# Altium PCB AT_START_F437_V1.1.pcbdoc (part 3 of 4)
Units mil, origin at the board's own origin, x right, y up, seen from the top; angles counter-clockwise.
Board outline 10746.75 x 3533.35 mil, 2 copper layers (Top Layer, Bottom Layer); 198 components, 235 nets, 885 pads, 1100 vias.
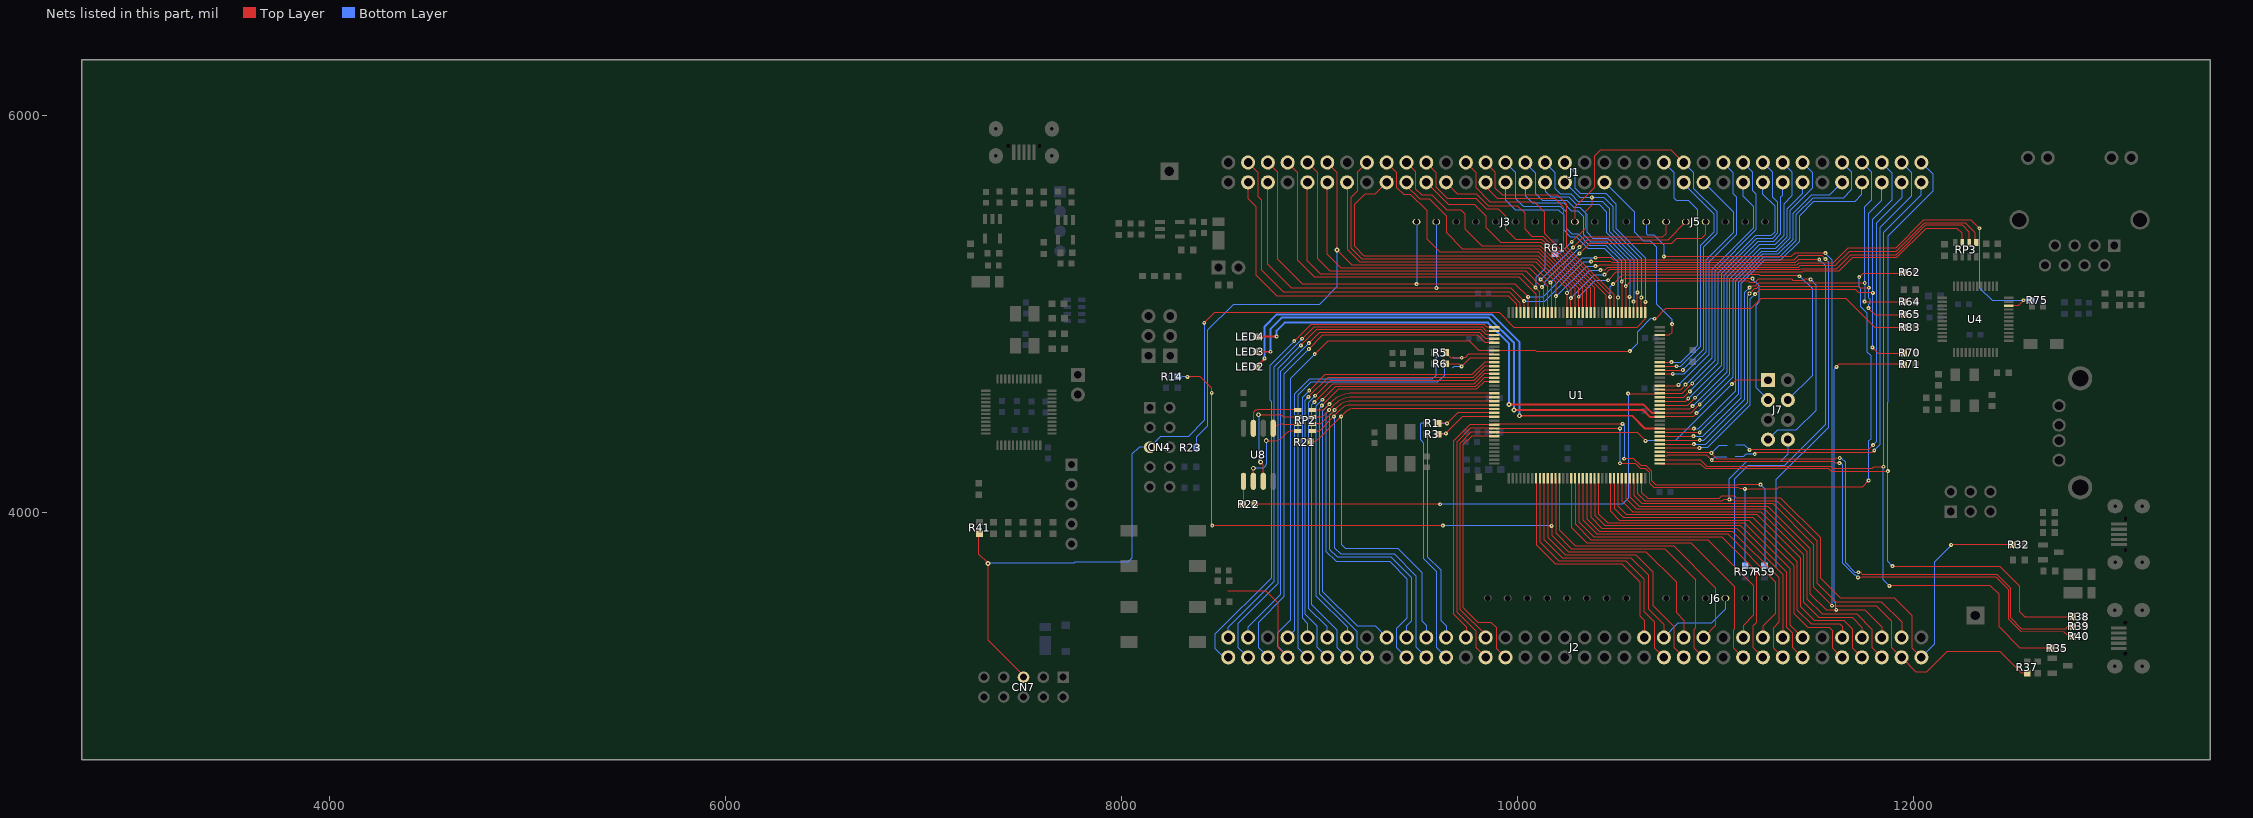
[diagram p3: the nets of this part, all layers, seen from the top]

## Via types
v1: diameter 19.69, hole 7.87, Top Layer to Bottom Layer, 1002 vias
v2: diameter 23.62, hole 11.81, Top Layer to Bottom Layer, 48 vias
v3: diameter 24, hole 12, Top Layer to Bottom Layer, 18 vias
v4: diameter 19.68, hole 7.87, Top Layer to Bottom Layer, 16 vias
v5: diameter 35.43, hole 19.69, Top Layer to Bottom Layer, 12 vias
v6: diameter 27.56, hole 15.75, Top Layer to Bottom Layer, 2 vias
v7: diameter 35.43, hole 19.68, Top Layer to Bottom Layer, 2 vias

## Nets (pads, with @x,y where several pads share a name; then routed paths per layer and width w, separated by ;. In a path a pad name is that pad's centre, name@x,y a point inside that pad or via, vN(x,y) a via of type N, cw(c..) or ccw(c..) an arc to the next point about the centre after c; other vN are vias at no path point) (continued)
PA14/SWCLK: CN4.5 CN7.5 J1.37 R41.1 U1.109 | length 6334.4
  Top Layer w6: R41.1@7280,3888.07 7280,3786.07 v2(7325.75,3740.36) 7325.8,3352.26 7505,3173.07 CN7.5@7505,3165.97 ; v1(8417.75,4955.35) 8470.3,5007.86 9907.4,5007.86 9980.9,4934.36 10603.03,4934.36 10644.2,4975.54 U1.109@10644.23,5007.69 10644.7,5008.16 v1@10644.7,5061.36
  Bottom Layer w6: v2@7325.7,3740.36 7757.8,3740.36 7763.8,3746.36 8030.8,3746.36 8054.8,3770.36 8054.8,4293.47 8088.8,4327.56 ; 8090.27,4327.36 CN4.5@8142.77,4327.36 8142.78,4329.84 8194.3,4381.36 8336.5,4381.36 8417.8,4462.66 v1(8417.75,4955.35) ; J1.37@10238.7,5765.06 10287.8,5715.97 10287.8,5637.27 10315.7,5609.36 10443.8,5609.36 10495.8,5557.36 10495.8,5433.97 10644.7,5285.06 v1@10644.7,5061.36
  other v1: 10644.75,5061.35
PA15: J1.38 R61.1 U1.110 | length 1263.8
  Top Layer w6: v1(10273.42,5364.4) 10340.4,5431.36 10340.4,5515.27 10374.5,5549.47 v1(10374.54,5589.36) ; U1.110@10624.54,5007.69 10624.7,5007.86 v1@10624.7,5083.36
  Bottom Layer w6: R61.1@10188.8,5306.86 10215.9,5306.86 v1(10273.42,5364.4) ; J1.38@10238.7,5665.06 10314.4,5589.36 v1(10374.54,5589.36) ; v1(10374.54,5589.36) 10435.8,5589.36 10479.8,5545.36 10479.8,5425.56 10624.7,5280.66 v1@10624.7,5083.36
  other v1: 10624.75,5083.35
PB0: J2.46 J6.4 U1.46 | length 1685.8
  Top Layer w6: U1.46@10132.42,4171.06 10132.4,3861.66 10224.2,3769.86 10572.3,3769.86 10659.5,3682.66 10659.5,3512.57 10738.7,3433.47 J2.46@10738.72,3366.46
  Bottom Layer w6: J2.46@10738.72,3366.46 10809.6,3437.36 10977.8,3437.36 11049.4,3508.97 J6.4@11049.36,3565.36
PB1: J2.47 U1.47 | length 1397.4
  Top Layer w6: U1.47@10152.1,4171.06 10152.1,3872.26 10239.5,3784.86 10595.3,3784.86 10682,3698.16 10682,3529.16 10787.8,3423.36 10787.8,3317.47 J2.47@10838.72,3266.46
PB2/BOOT1: J2.48 R14.2 U1.48 | length 3916.5
  Top Layer w6: v1(8332.75,4682.35) 8398,4682.36 8455.5,4624.86 v1(8455.49,4601.97) ; v1(8457.75,3931.36) v1(9622.75,3931.36) ; U1.48@10171.79,4171.06 10171.7,4171.06 10171.7,3930.36 10171.7,3883.36 10255.6,3799.47 10647.6,3799.47 10799.8,3647.26 10799.8,3493.26 10838.7,3454.36 J2.48@10838.72,3366.46
  Bottom Layer w6: R14.2@8282.3,4683.36 v1(8332.75,4682.35) ; v1(8455.49,4601.97) 8455.49,3933.62 v1(8457.75,3931.36) ; v1(9622.75,3931.36) 9623.75,3930.36 v1(10171.75,3930.36)
PB3: J1.61 J5.4 R23.2 U1.133 | length 4256.2
  Top Layer w6: J1.61@9038.7,5765.06 9087.8,5715.97 v3(9087.75,5323.35) 9161.8,5249.36 10074.74,5249.36 v1(10165.09,5159.02) ; v1(10165.09,5159.02) 10171.8,5152.36 U1.133@10171.79,5007.69 ; v1(10313.22,5306.09) 10364.8,5357.66 10778.9,5357.66 10803.7,5382.56 10928.6,5382.56 10949.3,5403.16 J5.4@10949.35,5465.35
  Bottom Layer w6: R23.2@8377.3,4325.56 8377.2,4376.97 8433.4,4433.36 8433.4,4918.06 8563,5047.66 8998.1,5047.66 9087.8,5137.36 v3@9087.8,5323.56 ; v1(10165.09,5159.02) 10312.17,5306.09 v1(10313.22,5306.09)
PB4: J1.62 J5.6 U1.134 | length 2465.4
  Top Layer w6: J1.62@9038.7,5665.06 9035.8,5662.06 9035.8,5305.36 9107.8,5233.36 10057.73,5233.36 v1(10116.22,5174.88) 10151.74,5139.35 ; 10151.7,5139.36 10151.7,5008.06 U1.134@10152.1,5007.69 ; v1(10280.12,5336.81) 10333.7,5390.36 10733.2,5390.36 10749.3,5406.47 J5.6@10749.35,5465.35
  Bottom Layer w6: v1(10116.22,5174.88) 10118.18,5174.87 v1(10280.12,5336.81)
PB5: J1.63 J5.5 U1.135 | length 2701.5
  Top Layer w6: J1.63@8938.7,5765.06 8987.8,5715.97 8987.8,5281.36 9051.8,5217.36 10041,5217.36 v1(10122.52,5135.88) 10132.4,5125.97 U1.135@10132.42,5007.69 ; v1(10312.43,5337.6) 10350.3,5375.47 10759.4,5375.47 J5.5@10849.35,5465.35
  Bottom Layer w6: v1(10122.52,5135.88) 10140.65,5154 10140.65,5165.42 10312.43,5337.21 v1(10312.43,5337.6)
PB6: J1.64 U1.136 | length 1936.9
  Top Layer w6: J1.64@8938.7,5665.06 8938.7,5268.47 9005.8,5201.36 10022.7,5201.36 10090.7,5133.36 10112.7,5111.36 U1.136@10112.73,5007.69
  Bottom Layer w6: v1@10090.7,5133.36 10090.7,5183.66 10135.7,5228.66 10135.7,5312.27
  other v1: 10090.75,5133.35
PB7: J1.65 U1.137 | length 1882.2
  Top Layer w6: J1.65@8838.7,5765.06 8889.8,5713.97 8889.8,5271.27 8975.8,5185.36 10008.9,5185.36 10093.1,5101.06 U1.137@10093.05,5007.69
PB8: J1.67 J3.10 U1.139 | length 5522.3
  Top Layer w6: J1.67@8738.7,5764.56 8787.8,5715.97 8787.8,5277.27 8913.8,5151.36 9988.8,5151.36 v1(10053.12,5087.01) 10053.1,5008.16 U1.139@10053.7,5007.56 ; v1(10393.75,5284.35) 10473.91,5284.35 10486.39,5271.87 11394.17,5271.87 11416.96,5294.66 11536.98,5294.66 v1(11553.92,5277.71)
  Bottom Layer w6: J3.10@9489.36,5465.36 9489.4,5393.77 9489.7,5393.47 v1@9489.7,5151.36 ; v1(10053.12,5087.01) 10129.44,5087.01 10326.8,5284.36 v1(10393.75,5284.35) ; 11306.54,3721.67 11306.54,4164.71 11570.8,4428.97 11570.8,5260.9 v1@11553.97,5277.72
  other v1: 9489.75,5151.35
PB9: J1.68 J3.9 U1.140 | length 5621
  Top Layer w6: J1.68@8738.7,5664.56 8738.7,5252.36 8859.8,5131.36 9966.7,5131.36 v1(10032.75,5065.35) 10032.8,5008.77 U1.140@10034,5007.56 ; v1(10370.75,5264.35) 10470.75,5264.35 10476.75,5258.35 11400.21,5258.35 11416.81,5274.96 v1(11523.19,5274.96)
  Bottom Layer w6: v1(9589.35,5131.35) J3.9@9589.36,5465.36 ; v1(10032.75,5065.35) 10135.75,5065.35 10334.75,5264.35 v1(10370.75,5264.35) ; 11095.8,3722.47 11095.8,4168.31 11165.05,4237.55 11347.86,4237.55 11554.8,4444.49 11554.8,5243.41 v1(11523.19,5274.96)
PB10: J2.69 J5.7 R37.1 U1.69 | length 5583.1
  Top Layer w6: U1.69@10585.17,4171.06 10585.2,4084.47 10626.4,4043.36 11287.9,4043.36 11492.9,3838.36 11492.9,3623.26 11588.2,3527.97 11810.2,3527.97 11887.8,3450.26 11887.8,3317.47 J2.69@11938.72,3266.46 12010.9,3194.26 12066.9,3194.26 12170.1,3297.47 12433.3,3297.47 12542.7,3188.07 R37.1@12572.7,3188.07 ; v1(10738.74,5290.72) 11382.48,5290.66 11401.45,5309.63 11552.35,5309.63 v1(11554.32,5307.66)
  Bottom Layer w6: J5.7@10649.35,5465.35 10649.3,5406.86 10655.6,5400.66 10686.7,5400.66 10738.7,5348.66 v1@10738.7,5290.77 ; v1(11554.32,5307.66) 11586.63,5275.35 11586.63,3527.91 v1(11587.37,3527.16)
PB11: J2.70 J7.8 U1.70 | length 2418.8
  Top Layer w6: U1.70@10604.86,4171.06 10604.9,4094.36 10642.6,4056.66 11034.3,4056.66 ; 11029.4,4056.66 11034.3,4056.66 ; v1(11068.91,4063.41) 11041.08,4063.45 11034.3,4056.66 ; v1(11068.91,4063.41) 11090.58,4063.41 11096.88,4057.1 11307.66,4057.1 11509.8,3854.97 11509.8,3643.66 11605.4,3548.07 11837.3,3548.07 11938.7,3446.66 J2.70@11938.72,3366.46
  Bottom Layer w6: v1(11068.91,4063.41) 11068.87,4167.78 11155.59,4254.5 11327.32,4254.5 11364.4,4291.49 J7.8@11364.4,4365.97
PB12/OTG2_ID: J1.1 R38.1 U1.73 | length 4427.2
  Top Layer w6: U1.73@10718.05,4244.88 10718.73,4244.25 10923.13,4244.25 10946.95,4220.43 11569.56,4220.43 11583.53,4206.47 v1@11869.5,4206.47 ; v1@11892.73,3727.34 12434.89,3727.34 12533.8,3628.43 12533.8,3498.8 12560.24,3472.36 R38.1@12807,3472.36
  Bottom Layer w6: 11868.8,4554.36 11868.8,5392.77 12095.8,5619.86 12095.8,5707.97 J1.1@12038.7,5765.06 ; 11869.75,4553.36 11869.52,4553.13 v1(11869.52,4206.43) 11869.52,3750.57 v1(11892.76,3727.32)
PB13/OTG2_VBUS: J1.2 R35.1 U1.74 | length 4325.7
  Top Layer w6: U1.74@10718.05,4264.56 10718.32,4264.35 10922.34,4264.35 10954.26,4232.43 11580.7,4232.43 11592.13,4221.01 11791.1,4221.01 11798.98,4228.89 v1(11847.45,4228.89) ; v1@11876.99,3627.67 12387.2,3627.67 12430.97,3583.91 12430.97,3420.4 12537.8,3313.57 R35.1@12697.2,3313.57
  Bottom Layer w6: v1@11847.4,4228.86 11848.8,4230.27 11848.8,5413.06 12038.7,5602.97 J1.2@12038.7,5665.06 ; v1(11847.45,4228.89) 11847.45,3657.19 v1(11877,3627.64)
PB14/OTG2_D-: R40.1 U1.75 | length 2931.1
  Top Layer w6: U1.75@10718.05,4284.24 10755.7,4284.24 10759.05,4287.59 10955.1,4287.59 v1(10980.26,4262.38) 10988.06,4254.64 11597.51,4254.64 11605.14,4247.01 v1(11624.45,4247.01) ; v1(11718.62,3670.19) 11732.05,3670.23 11736.38,3674.57 12413.03,3674.57 12477.67,3609.92 12477.67,3460.74 12541.21,3397.07 12757.8,3395.18 12784.61,3372.57 12804.63,3372.57 R40.1@12804.85,3372.35
  Bottom Layer w6: v1(10980.26,4262.38) 10998.25,4280.36 11055.6,4280.36 ; v1(11624.45,4247.01) 11633.91,4247.01 11639.42,4241.49 11639.42,3743.08 11699.07,3683.44 11705.37,3683.44 v1(11718.62,3670.19)
PB14_E: J1.3 | length 2265.7
  Top Layer w6: v1@11197.39,4292.35 11203.39,4298.35 11787.3,4298.35 v1(11800.57,4311.63)
  Bottom Layer w6: 11100,4280.36 11140.5,4280.36 11152.4,4292.36 v1@11197.4,4292.36 ; v1@11800.52,4311.64 11831.8,4342.92 11831.8,5436.97 11988.8,5593.97 11988.8,5714.97 J1.3@11938.7,5765.06
  other v1: 11197.35,4292.31
PB15/OTG2_D+: R39.1 U1.76 | length 2949.3
  Top Layer w6: U1.76@10718.05,4303.94 10753.39,4303.94 10757.73,4299.59 10976.09,4299.59 11009.14,4266.64 11603.1,4266.64 11609.48,4273.01 v1(11626.42,4273.01) ; v1(11720.59,3696.2) 11731.65,3696.16 11741.25,3686.57 12418.1,3686.57 12489.67,3614.99 12489.67,3465.69 12546.35,3409.02 12765.13,3409.02 12778.48,3422.37 R39.1@12804.83,3422.37
  Bottom Layer w6: v1(10978.29,4298.23) 11018.47,4338.36 11057.6,4338.36 ; v1(11626.42,4273.01) 11634.91,4273.01 11654,4253.92 11654,3745.48 11703.28,3696.2 v1(11720.59,3696.2)
PB15_E: J1.4 | length 2099
  Top Layer w6: v1(11171.75,4314.35) 11770.94,4314.36 v1@11794.61,4338.03
  Bottom Layer w6: 11102,4338.36 11147.8,4338.36 v1(11171.75,4314.35) ; v1@11794.61,4338.03 11813.8,4357.23 11813.8,5461.47 11938.7,5586.47 J1.4@11938.7,5665.06
  other v1: 11794.66,4338.02
PC0: J2.26 R59.1 U1.26 | length 3281.1
  Top Layer w6: J2.26@9738.72,3366.46 9739.8,3367.47 9739.8,3420.97 9673.8,3486.97 9673.8,4358.47 9757,4441.66 U1.26@9881.43,4441.73 9885.1,4445.36 v1@10529.7,4445.36 ; v1(10537.75,4269.35) 10587.05,4269.35 10623.45,4232.95 10650.39,4232.95 10677.85,4205.49 10677.85,4158.97 10701.2,4135.62 11106.06,4135.62 11107.92,4137.48 11225.72,4137.48 v1(11226.51,4138.27)
  Bottom Layer w6: v1@10529.75,4445.35 10537.75,4437.35 v1(10537.75,4269.35) ; v1(11226.51,4138.27) 11246.6,4118.17 R59.1@11246.6,3729.01
  other v1: 10529.75,4445.35
PC1: J2.27 R57.1 R62.1 U1.27 | length 5214
  Top Layer w6: J2.27@9838.72,3266.46 9787.8,3317.47 9787.8,3401.26 9691.5,3497.57 9691.5,4351.86 9761.7,4422.06 9881.4,4422.06 9881.8,4422.36 v1@10516.7,4422.36 ; v1@10516.7,4246.36 10593.07,4246.36 10618.48,4220.95 10645.42,4220.95 10665.85,4200.52 10665.85,4147.72 10689.95,4123.62 11117.7,4123.62 11123.95,4117.36 v1(11147.71,4117.38) 11310.41,4117.36 11319.1,4126.05 11739.1,4126.05 v1(11772.59,4159.54) ; v1(11724.92,5186.31) 11745.83,5207.19 R62.1@11948.12,5207.19
  Bottom Layer w6: v1(10516.75,4246.35) v1@10516.75,4422.35 ; v1@11147.76,4117.39 11147.76,3728.81 R57.1@11149.7,3726.86 ; v1(11724.92,5186.31) 11724.92,5135.31 11732.41,5127.82 11732.41,5037.37 11766.29,5003.49 11766.29,4808.07 11784.41,4789.94 11784.41,4371.12 11772.59,4359.3 v1(11772.59,4159.54)
  other v1: 10516.75,4422.35
PC2: J2.28 J7.1 U1.28 | length 2759
  Top Layer w6: J2.28@9838.72,3366.46 9838.7,3379.36 9707.6,3510.47 9707.6,4345.47 9764.5,4402.36 U1.28@9881.43,4402.35 10565.8,4402.36 10603.76,4402.35 10645.75,4360.36 v1(10645.75,4359.35) ; v1(11081.75,4646.35) 11101.3,4665.97 J7.1@11264.4,4665.97
  Bottom Layer w6: v1(10645.75,4359.35) 10794.75,4359.35 10836.76,4401.36 v1(11081.75,4646.35)
PC3: J2.29 U1.29 | length 1376.1
  Top Layer w6: U1.29@9881.43,4382.68 9767.1,4382.66 9723.8,4339.36 9723.8,3519.26 9798.7,3444.36 9864.8,3444.36 9891.8,3417.26 9891.8,3313.47 J2.29@9938.72,3266.46
PC4: J2.44 U1.44 | length 1227.3
  Top Layer w6: U1.44@10093.05,4171.06 10093.1,3834.36 10189.1,3738.36 10524.8,3738.36 10615.8,3647.36 10615.8,3477.57 10638.9,3454.36 J2.44@10638.72,3366.46
PC5: J2.45 U1.45 | length 1362.3
  Top Layer w6: U1.45@10112.73,4171.06 10112.7,3849.76 10207.6,3754.86 10546.3,3754.86 10637.8,3663.36 10637.8,3499.36 10689.8,3447.36 10689.8,3315.47 J2.45@10738.72,3266.46
PC6: J1.24 U1.96 | length 1257.2
  Top Layer w6: U1.96@10718.1,4697.66 10783.12,4697.66 v1@10783.21,4697.76
  Bottom Layer w6: v1@10783.21,4697.76 10841.58,4697.76 10953.5,4809.68 10953.5,5275.06 11091,5412.56 11091,5512.77 J1.24@10938.7,5665.06
  other v1: 10783.26,4697.75
PC7: J1.25 J3.2 U1.97 | length 2167
  Top Layer w6: J3.2@10289.36,5465.36 10289.4,5538.97 10387.8,5637.36 10387.8,5797.36 10417.8,5827.36 10776.4,5827.36 J1.25@10838.7,5765.06 ; U1.97@10718.05,4717.31 10833.84,4717.27 v1@10834.04,4717.46
  Bottom Layer w6: v1@10834.04,4717.46 10939.3,4822.72 10939.3,5340.86 11007.1,5408.56 11007.1,5516.16 10889.8,5633.36 10889.8,5713.97 J1.25@10838.7,5765.06
  other v1: 10834.09,4717.45
PC8: J1.26 U1.98 | length 1168.5
  Top Layer w6: U1.98@10718.05,4737.01 10802.31,4736.97 v1@10802.91,4736.37
  Bottom Layer w6: v1@10802.91,4736.37 10824.25,4736.37 10924.7,4836.82 10924.7,5348.16 10992.5,5415.97 10992.5,5504.56 10838.7,5658.36 J1.26@10838.7,5665.06
  other v1: 10802.96,4736.36
PC9: J1.27 U1.99 | length 1255
  Top Layer w6: U1.99@10718.05,4756.69 10776.32,4756.66 v1@10776.51,4756.86
  Bottom Layer w6: J1.27@10738.7,5765.06 10789.8,5713.97 10789.8,5585.56 10804.5,5570.86 10865.2,5570.86 10909.3,5526.77 10909.3,4843.49 10822.67,4756.86 v1@10776.51,4756.86
  other v1: 10776.56,4756.85
PC10: J1.39 U1.111 | length 1052.5
  Top Layer w6: v1@10604.7,5109.36 10604.7,5007.77 U1.111@10604.86,5007.69
  Bottom Layer w6: J1.39@10138.7,5765.06 10187.8,5715.97 10187.8,5635.36 10215.8,5607.36 10267.8,5607.36 10304.8,5570.36 10426.8,5570.36 10463.8,5533.36 10463.8,5418.27 10604.7,5277.47 v1@10604.7,5109.36
  other v1: 10604.75,5109.35
PC11: J1.40 U1.112 | length 963.4
  Top Layer w6: U1.112@10585.17,5007.69 10585.7,5008.27 v1@10585.7,5062.36
  Bottom Layer w6: J1.40@10138.7,5665.06 10138.7,5620.36 10167.8,5591.36 10257.7,5591.36 10295.7,5553.36 10411.7,5553.36 10447.7,5517.36 10447.7,5412.27 10585.7,5274.36 v1@10585.7,5062.36
  other v1: 10585.75,5062.35
PC12: J1.41 U1.113 | length 1108.7
  Top Layer w6: U1.113@10565.49,5007.69 10565.7,5007.97 v1@10565.7,5086.36
  Bottom Layer w6: J1.41@10038.7,5765.06 10089.8,5713.97 10089.8,5609.27 10123.8,5575.36 10246.8,5575.36 10283.8,5538.36 10312.8,5538.36 10347.8,5503.36 10347.8,5414.97 10380.2,5382.56 10455.1,5382.56 10565.7,5271.86 v1@10565.7,5086.36
  other v1: 10565.75,5086.35
PC13: J2.7 R83.1 U1.7 | length 5437.4
  Top Layer w6: 8536,3602.36 8727.8,3602.36 8788.8,3541.36 8788.8,3316.47 J2.7@8838.72,3266.46 ; v1@8975.7,4797.36 9044.3,4865.97 9754.9,4865.97 9805.1,4815.77 U1.7@9881.4,4815.77 ; U1.7@9881.43,4815.74 10091.9,4815.74 10097.9,4809.74 10563.91,4809.74 v4(10566.56,4812.4) ; v4(10691.85,4976.3) 10696.19,4976.3 10748.98,5029.1 11178.86,5029.1 11228.9,5079.14 11657.55,5079.14 11803.72,4932.96 R83.1@11950.97,4932.96
  Bottom Layer w6: J2.7@8838.7,3266.57 8838.7,3270.36 8787.8,3321.57 8787.8,3391.27 8853.75,3457.22 8853.75,4675.36 v1(8975.75,4797.35) ; v4(10566.56,4812.4) 10605.57,4851.41 10605.57,4911.29 10670.58,4976.3 v4(10691.85,4976.3)
PC14/LEXT_IN: R5.2 U1.8 | length 309.7
  Top Layer w6: R5.2@9635.8,4805.27 9661.8,4779.36 v1(9717.75,4779.35) 9734.5,4779.36 9751.2,4796.06 U1.8@9881.43,4796.06
  Bottom Layer w6: 9673,4783.36 9677,4779.36 v1(9717.75,4779.35)
PC14_E: J2.8 | length 2127.9
  Bottom Layer w6: J2.8@8838.7,3366.57 8871.8,3399.66 8871.8,4594.36 8947.2,4669.77 9567.4,4669.77 9586.7,4689.06 9586.7,4776.56 9593.5,4783.36 9628.6,4783.36
PC15/LEXT_OUT: R6.2 U1.9 | length 314
  Top Layer w6: R6.2@9636.6,4748.56 9704.9,4748.56 v1(9717.49,4735.97) 9757.9,4776.36 U1.9@9881.43,4776.38
  Bottom Layer w6: 9673,4729.36 9679.6,4735.97 v1(9717.49,4735.97)
PC15_E: J2.9 | length 2164.2
  Bottom Layer w6: J2.9@8938.72,3266.46 8890.1,3315.07 8890.1,4590.16 8954.7,4654.77 9595.3,4654.77 9628.6,4688.06 9628.6,4729.36
PD0: J1.42 J7.7 U1.114 | length 2957.9
  Top Layer w6: v1@10545.63,5140.61 10545.63,5007.84 U1.114@10545.8,5007.69 ; v1(10545.68,5140.6) 10570.11,5165.03 11167.2,5165.03 11173.96,5158.26 11197.29,5158.26 11213.97,5174.95 11386.87,5174.95 11392.87,5168.95 11442.01,5168.95 11448.01,5174.95 11479,5174.95 v1(11479.46,5174.49)
  Bottom Layer w6: J1.42@10038.7,5665.06 10038.7,5596.36 10073.8,5561.36 10231.8,5561.36 10271.7,5521.36 10303.8,5521.36 10331.8,5493.36 10331.8,5403.97 10369.8,5365.97 10449.1,5365.97 10545.63,5269.44 v1@10545.63,5140.61 ; J7.7@11264.4,4365.97 11313.8,4415.36 11407.8,4415.36 11505.07,4512.63 11505.07,5148.88 v1(11479.46,5174.49)
PD1: J1.43 J7.3 U1.115 | length 2504.9
  Top Layer w6: U1.115@10526.12,5007.69 10525.93,5007.84 10525.93,5163.46 10542.07,5179.61 11185.14,5179.61 v1(11185.93,5178.82)
  Bottom Layer w6: J1.43@9938.7,5765.06 9987.8,5715.97 9987.8,5585.27 10027.8,5545.36 10215.8,5545.36 10245.8,5515.36 10245.8,5433.27 10273.3,5405.77 10305.4,5405.77 10362.8,5348.36 10445.5,5348.36 10525.93,5267.94 v1@10525.93,5163.46 ; v1(11185.93,5178.82) 11185.94,5176.84 11220.99,5141.78 11220.99,5062.59 11203.66,5045.25 11203.66,4626.71 J7.3@11264.4,4565.97
  other v1: 10525.98,5163.45
PD2: J1.44 U1.116 | length 1087.8
  Top Layer w6: U1.116@10506.43,5007.69 10506.7,5007.97 v1@10506.7,5083.36
  Bottom Layer w6: J1.44@9938.7,5665.06 9938.7,5576.36 9987.8,5527.36 10205.8,5527.36 10231.8,5501.36 10231.8,5424.36 10266.3,5389.86 10296.3,5389.86 10353.8,5332.36 10438.6,5332.36 10506.7,5264.27 v1@10506.7,5083.36
  other v1: 10506.75,5083.35
PD3: J1.45 U1.117 | length 1188.7
  Top Layer w6: J1.45@9838.72,5765.03 9887.76,5716 9887.76,5641.35 ; 9887.8,5641.36 9887.8,5635.27 9923.7,5599.36 10201.7,5599.36 10247.8,5553.36 10247.8,5336.36 10486.8,5097.27 U1.117@10486.75,5007.69
PD4: J1.46 J7.4 U1.118 | length 2825.7
  Top Layer w6: J1.46@9838.7,5665.06 9838.7,5642.36 9899.7,5581.36 10189.8,5581.36 10231.8,5539.36 10231.8,5333.36 10467.1,5097.97 v1(10467.1,5086.84) U1.118@10467.06,5007.69 ; v1(10481.75,5151.35) 10525.37,5194.97 11158.68,5194.97 11162.06,5198.35 11219.09,5198.35 11225.09,5192.35 11421.4,5192.35 v1(11422.72,5191.03)
  Bottom Layer w6: v1(10467.1,5086.84) 10467.1,5136.71 v1(10481.75,5151.35) ; J7.4@11364.4,4565.97 11486.94,4688.51 11486.94,5129.57 11425.48,5191.03 v1(11422.72,5191.03)
PD5: J1.47 U1.119 | length 1182.1
  Top Layer w6: J1.47@9738.7,5765.06 9789.8,5713.97 9789.8,5637.36 9861.8,5565.36 10085.8,5565.36 10137.8,5513.36 10137.8,5404.36 10447.4,5094.66 U1.119@10447.38,5007.69
PD6: J1.50 U1.122 | length 1167.3
  Top Layer w6: J1.50@9655.75,5648 J1.50@9638.72,5665.03 9698.4,5605.36 9793.8,5605.36 9853.8,5545.36 10001.8,5545.36 10037.8,5509.27 10037.8,5427.36 10073.8,5391.36 10129.8,5391.36 10388.3,5132.77 U1.122@10388.32,5007.69
PD7: J1.51 U1.123 | length 1298.3
  Top Layer w6: J1.51@9538.7,5765.06 9589.8,5713.97 9589.8,5639.97 9646.4,5583.36 9789.8,5583.36 9843.8,5529.36 9903.8,5529.36 9939.8,5493.36 9939.8,5427.27 9991.8,5375.36 10124.8,5375.36 10368.7,5131.36 U1.123@10368.7,5007.66
PD8: J1.5 R70.1 U1.77 | length 2897.4
  Top Layer w6: U1.77@10718.05,4323.61 v1(10917.75,4323.6) ; v4(11198.93,5100.41) 11221.78,5123.27 11707.41,5123.27 11723.56,5107.11 v4(11793.48,5107.11) ; v1@11791.56,4831.72 11821.51,4801.76 R70.1@11954.8,4801.76
  Bottom Layer w6: v1(10917.75,4323.6) 10957,4323.56 11172.53,4539.1 11172.53,5073.96 v4@11198.99,5100.41 ; v1@11791.56,4831.72 11793.48,4833.64 v4(11793.48,5107.11) 11793.48,5477.47 11889.61,5573.61 11889.61,5714.14 J1.5@11838.72,5765.03
  other v1: 11791.51,4831.71
PD9: J1.6 R65.1 U1.78 | length 2567.5
  Top Layer w6: U1.78@10718.05,4343.31 v1(10889.75,4343.3) ; v4(11170.96,5103.57) 11198.42,5131.03 11208.67,5131.03 11217.05,5139.42 11723.19,5139.42 11729.89,5132.72 v1(11773.78,5132.72) ; v1(11771.02,5030.28) 11806.08,4995.22 11947.81,4995.22 R65.1@11950.97,4998.37
  Bottom Layer w6: v1(10889.75,4343.3) 10949.7,4343.27 11158.35,4551.91 11158.35,5090.96 v4(11170.96,5103.57) ; v1(11771.02,5030.28) 11771.02,5047.22 11777.02,5053.22 11777.02,5077.19 11771.02,5083.19 11771.02,5129.96 v1(11773.78,5132.72) 11773.78,5508.6 11838.72,5573.54 J1.6@11838.72,5665.03
PD10: J1.7 R64.1 U1.79 | length 2616.1
  Top Layer w6: U1.79@10718.05,4362.98 10718.4,4363.36 v1(10919.75,4363.35) ; v4(11171.74,5133.51) 11181.27,5143.03 11201.76,5143.03 11214.36,5155.64 11751.78,5155.64 v1(11752.89,5156.76) ; v1(11752.5,5062.98) 11753.29,5062.2 R64.1@11950.97,5062.2
  Bottom Layer w6: v1(10919.75,4363.35) 10940.8,4363.36 11144.95,4567.52 11144.95,5106.69 v4@11171.77,5133.51 ; J1.7@11738.72,5765.03 11788.75,5715.01 11788.75,5577.55 11752.89,5541.69 v1(11752.89,5156.76) 11752.89,5063.38 v1(11752.5,5062.98)
PD11: J1.8 U1.80 | length 2001.5
  Top Layer w6: U1.80@10718.05,4382.68 10718.8,4383.36 v1(10887.75,4383.35)
  Bottom Layer w6: v1(10887.75,4383.35) 10934.8,4383.36 11129.8,4578.36 11129.8,5155.36 11247.8,5273.36 11329.8,5273.36 11423.8,5367.36 11423.8,5497.36 11495.8,5569.36 11703.7,5569.36 11738.7,5604.36 J1.8@11738.7,5665.06
PD12: J1.9 U1.81 | length 2039.9
  Top Layer w6: U1.81@10718.05,4402.35 v1@10919.8,4402.36
  Bottom Layer w6: v1@10919.8,4402.36 11115.8,4598.36 11115.8,5161.36 11243.8,5289.36 11323.8,5289.36 11407.8,5373.36 11407.8,5503.36 11491.8,5587.36 11645.8,5587.36 11687.8,5629.36 11687.8,5715.97 J1.9@11638.7,5765.06
  other v1: 10919.75,4402.34
PD13: J1.10 LED2.2 U1.82 | length 4534.7
  Top Layer w6: U1.82@10718.1,4422.06 10718.7,4421.36 v1@10889.7,4421.36
  Top Layer w10: LED2.2@8681.5,4734.56 8722.2,4775.27 v1@8722.2,4775.77 ; v2@10009.7,4486.36 10577.8,4486.36 10642,4422.06 U1.82@10718.1,4422.06
  Bottom Layer w6: v1@10889.7,4421.36 10910.8,4421.36 11101.8,4612.36 11101.8,5167.36 11237.8,5303.36 11316.4,5303.36 11391.8,5378.77 11391.8,5509.36 11485.8,5603.36 11577,5603.36 J1.10@11638.7,5665.06
  Bottom Layer w10: v1@8722.2,4775.77 8722.2,4936.97 8784.1,4998.77 9868.3,4998.77 10009.7,4857.36 v2@10009.7,4486.36
  other v1: 10889.75,4421.35 8722.25,4775.76
  other v2: 10009.75,4486.35
PD14: J1.13 LED3.2 U1.85 | length 4352
  Top Layer w6: U1.85@10718.05,4481.1 10718.1,4484.16 10888.6,4484.16 v1(10903.75,4499.35)
  Top Layer w10: LED3.2@8681.56,4809.56 v1@8752.2,4809.66 ; v2@9981.7,4515.36 10633.7,4515.36 10668,4481.06 U1.85@10718.05,4481.1
  Bottom Layer w6: v1(10903.75,4499.35) 11087.8,4683.36 11087.8,5173.36 11231.8,5317.36 11308.7,5317.36 11375.8,5384.47 11375.8,5523.86 11489.8,5637.97 11489.8,5713.97 J1.13@11438.7,5765.06
  Bottom Layer w10: v1@8752.2,4809.66 8752.2,4925.47 8808.6,4981.86 9855.2,4981.86 9981.7,4855.36 v2@9981.7,4515.36
  other v1: 8752.19,4809.65
  other v2: 9981.75,4515.35
PD15: J1.14 LED4.2 U1.86 | length 4078.2
  Top Layer w6: U1.86@10718.05,4500.78 10877.2,4500.77 v1@10919.7,4543.36 ; J1.14@11438.7,5640.06 J1.14@11438.7,5665.06
  Top Layer w10: LED4.2@8681.56,4885.86 v1(8782.92,4886.48) ; v2@9956.7,4543.36 10635.3,4543.36 10677.9,4500.77 U1.86@10718.05,4500.78
  Bottom Layer w6: v1@10919.7,4543.36 11071.8,4695.36 11071.8,5179.36 11225.8,5333.36 11303,5333.36 11360.3,5390.66 11360.3,5531.66 11438.7,5610.06 J1.14@11438.7,5665.06
  Bottom Layer w10: v1(8782.92,4886.48) 8782.9,4916.36 8823.5,4956.97 9850.1,4956.97 9956.7,4850.36 v2@9956.7,4543.36
  other v1: 10919.75,4543.35
  other v2: 9956.75,4543.35
PE0: J1.69 U1.141 | length 1994.3
  Top Layer w6: J1.69@8638.7,5764.56 8689.8,5713.97 8689.8,5593.27 8708.5,5574.56 8708.5,5220.66 8819.8,5109.36 9959.1,5109.36 10014.3,5054.16 U1.141@10014.3,5007.56
PE1: J1.70 U1.142 | length 1904
  Top Layer w6: J1.70@8638.7,5664.56 8638.7,5582.36 8679.8,5541.27 8679.8,5195.27 8785.8,5089.36 9955.8,5089.36 9994.6,5050.56 U1.142@9994.6,5007.56
PE2: J2.1 U1.1 | length 2861.3
  Top Layer w6: v1@8871.7,4863.36 8957.9,4949.47 9827.8,4949.47 9843.5,4933.86 U1.1@9881.43,4933.85
  Bottom Layer w6: J2.1@8538.72,3266.46 8516.7,3266.47 8471.8,3311.36 8471.8,3383.36 8755.5,3667.07 8755.5,4560.56 8747.8,4568.16 8747.8,4739.36 v1@8871.7,4863.36
  other v1: 8871.75,4863.35
PE3: J2.2 U1.2 | length 2666.9
  Top Layer w6: v1@8911.7,4875.36 8972.1,4935.77 9820.3,4935.77 9841.9,4914.16 U1.2@9881.43,4914.16
  Bottom Layer w6: J2.2@8538.7,3366.57 8538.7,3418.86 8769.8,3649.97 8769.8,4733.36 v1@8911.7,4875.36
  other v1: 8911.75,4875.35
PE4: J2.3 U1.3 | length 2748.1
  Top Layer w6: v1@8905.7,4841.36 8986.3,4921.97 9812.8,4921.97 9840.3,4894.47 U1.3@9881.43,4894.48
  Bottom Layer w6: J2.3@8638.72,3266.46 8587.8,3317.47 8587.8,3436.86 8787.8,3636.86 8787.8,4723.36 v1@8905.7,4841.36
  other v1: 8905.75,4841.35
PE5: J2.4 U1.4 | length 2586.6
  Top Layer w6: v1@8945.7,4853.36 9000.9,4908.56 9804.9,4908.56 9838.7,4874.77 U1.4@9881.43,4874.8
  Bottom Layer w6: J2.4@8638.72,3366.46 8638.7,3420.76 8803.8,3585.86 8803.8,4711.36 v1@8945.7,4853.36
  other v1: 8945.75,4853.35
PE6: J2.5 U1.5 | length 2663.3
  Top Layer w6: v1@8945.7,4823.36 9017.1,4894.77 9795.5,4894.77 9835.2,4855.06 U1.5@9881.43,4855.11
  Bottom Layer w6: J2.5@8738.7,3266.57 8691.5,3313.76 8691.5,3443.66 8821.8,3573.97 8821.8,4699.36 v1@8945.7,4823.36
  other v1: 8945.75,4823.35
PE7: J2.58 U1.58 | length 1605.7
  Top Layer w6: U1.58@10368.7,4171.06 10368.7,3975.26 10425.6,3918.36 11107.2,3918.36 11338.7,3686.86 J2.58@11338.72,3366.46
PE8: J2.59 U1.59 | length 1740.3
  Top Layer w6: U1.59@10388.32,4171.06 10388.3,3983.57 10439.5,3932.36 11123.5,3932.36 11357.5,3698.36 11357.5,3421.47 11387.8,3391.07 11387.8,3317.47 J2.59@11438.72,3266.46
PE9: J2.60 U1.60 | length 1635.5
  Top Layer w6: U1.60@10408.01,4171.06 10408,3992.07 10454.9,3945.16 11144.6,3945.16 11374.3,3715.47 11374.3,3430.86 J2.60@11438.72,3366.46
PE10: J2.63 U1.63 | length 1835.9
  Top Layer w6: U1.63@10467.06,4171.06 10467.1,4006.07 10513.8,3959.36 11166.2,3959.36 11393.2,3732.47 11393.2,3489.97 11463.8,3419.36 11572.7,3419.36 11589.8,3402.26 11589.8,3315.47 J2.63@11638.72,3266.46
PE11: J2.64 U1.64 | length 1749.5
  Top Layer w6: U1.64@10486.75,4171.06 10486.8,4020.26 10533.5,3973.57 11187.9,3973.57 11410.1,3751.36 11410.1,3507.57 11482.3,3435.36 11626.4,3435.36 11638.7,3423.07 J2.64@11638.72,3366.46
PE12: J2.65 U1.65 | length 1887.8
  Top Layer w6: U1.65@10506.43,4171.06 10506.4,4030.66 10549.3,3987.76 11208,3987.76 11427.4,3768.36 11427.4,3525.36 11498.4,3454.36 11646.8,3454.36 11689.8,3411.36 11689.8,3315.47 J2.65@11738.72,3266.46
PE13: J2.66 U1.66 | length 1784.8
  Top Layer w6: U1.66@10526.12,4171.06 10526.1,4055.97 10580.1,4001.97 11226.9,4001.97 11442.8,3786.07 11442.8,3546.16 11519.6,3469.36 11688.6,3469.36 11738.7,3419.26 J2.66@11738.72,3366.46
PE14: J2.67 U1.67 | length 1920.6
  Top Layer w6: U1.67@10545.8,4171.06 10545.8,4069.26 10598.9,4016.16 11245,4016.16 11460.2,3800.97 11460.2,3562.16 11537,3485.36 11711.2,3485.36 11787.8,3408.76 11787.8,3317.47 J2.67@11838.72,3266.46
PE15: J2.68 R71.1 U1.68 | length 3413.4
  Top Layer w6: U1.68@10565.49,4171.06 10565.5,4078.57 10613.8,4030.36 11263.5,4030.36 11475.9,3817.97 11475.9,3587.86 11557.5,3506.26 11753.7,3506.26 11838.7,3421.26 J2.68@11838.72,3366.46 ; v1(11609.48,4732.81) 11624.48,4747.78 11949.78,4747.78 R71.1@11952.2,4745.36
  Bottom Layer w6: v1(11609.08,3505.89) 11606.21,3508.76 11606.21,3539.34 11598.63,3546.92 11598.63,4722.35 11609.06,4732.79 v1(11609.48,4732.81)
PF0: J2.10 U1.10 | length 2266
  Top Layer w6: v1(8947.75,4613.35) 9026.7,4692.27 9768.7,4692.27 9833.1,4756.66 U1.10@9881.43,4756.69
  Bottom Layer w6: J2.10@8938.8,3366.47 8938.8,3438.36 8911.8,3465.26 8911.8,4577.36 v1(8947.75,4613.35)
PF1: J2.11 U1.11 | length 2370.2
  Top Layer w6: v1(8943.75,4581.35) 9040.1,4677.66 9772.1,4677.66 9831.4,4736.97 U1.11@9881.43,4737.01
  Bottom Layer w6: v1(8943.75,4581.35) 8926.9,4564.47 8926.9,3484.16 8987.8,3423.26 8987.8,3317.47 J2.11@9038.7,3266.57
PF2: J2.12 U1.12 | length 2230
  Top Layer w6: v1(8977.75,4587.35) 9053.9,4663.47 9777.9,4663.47 9831.7,4717.27 U1.12@9881.43,4717.31
  Bottom Layer w6: v1(8977.75,4587.35) 8945.8,4555.36 8945.8,3512.86 9038.7,3419.86 J2.12@9038.72,3366.46
PF3: J2.13 U1.13 | length 2334.4
  Top Layer w6: v1(8973.75,4555.35) 9066.5,4648.06 9781.3,4648.06 9830.9,4697.66 U1.13@9881.4,4697.66
  Bottom Layer w6: v1(8973.75,4555.35) 8960.8,4542.36 8960.8,3532.97 9089.8,3403.86 9089.8,3315.57 J2.13@9138.7,3266.57
PF4: J2.14 U1.14 | length 2192.5
  Top Layer w6: v1(9013.75,4567.35) 9080,4633.56 9785.9,4633.56 9830.3,4677.97 U1.14@9881.4,4677.97
  Bottom Layer w6: v1(9013.75,4567.35) 8981.8,4535.36 8981.8,3578.07 9138.7,3421.16 J2.14@9138.7,3366.57
PF5: J2.15 U1.15 | length 2295.9
  Top Layer w6: v1@9011.7,4537.36 9093.7,4619.36 9791.8,4619.36 9830.7,4658.27 U1.15@9881.43,4658.27
  Bottom Layer w6: v1@9011.7,4537.36 8997.8,4522.56 8997.8,3587.36 9187.8,3397.26 9187.8,3317.47 J2.15@9238.72,3266.46
  other v1: 9011.75,4537.35
PF6: J2.18 RP2.4 U1.18 | length 2327.2
  Top Layer w6: RP2.4@8962.7,4515.56 9008,4515.56 ; 9007.97,4515.53 ccw(c9007.97,4544.41) 9028.38,4523.99 9049.74,4545.35 cw(c9165.94,4448.7) 9179.76,4599.21 ; 9179.8,4599.16 U1.18@9881.43,4599.2
  Bottom Layer w6: v1@9049.7,4545.36 9013.8,4509.36 9013.8,3601.26 9189.8,3425.26 9279.9,3425.26 J2.18@9338.7,3366.57
  other v1: 9049.75,4545.35
PF7: J2.19 RP2.3 U1.19 | length 2580.1
  Top Layer w6: RP2.3@8962.73,4480.1 ccw(c8963.31,4480.69) 8963.31,4479.86 8996.5,4479.86 ; 8996.47,4479.86 ccw(c8996.47,4517.98) 9023.43,4491.03 ; 9023.42,4491.03 v1(9047.75,4515.35) cw(c9047.82,4515.36) v1(9047.75,4515.35) 9070.54,4538.18 9076.81,4544.44 cw(c9161.56,4459.69) 9161.56,4579.55 9170.4,4579.56 U1.19@9881.4,4579.56 ; 9170.32,4579.55 cw(c9170.32,4579.47) 9170.37,4579.52
  Bottom Layer w6: v1(9047.75,4515.35) 9031.8,4499.36 9031.8,3803.26 9084.1,3750.97 9354.6,3750.97 9441.3,3664.26 9441.3,3464.16 9387.8,3410.66 9387.8,3317.47 J2.19@9438.7,3266.57
PF8: J2.20 RP2.2 U1.20 | length 2460.9
  Top Layer w6: RP2.2@8962.73,4444.66 cw(c8964,4443.39) RP2.2@8964,4445.19 ; RP2.2@8964,4445.16 8993.7,4445.16 ; 8993.71,4445.19 ccw(c8993.71,4473.86) 9013.99,4453.59 v1(9075.75,4515.35) 9094.37,4533.98 cw(c9156.83,4471.52) 9156.83,4559.85 9183.1,4559.86 U1.20@9881.4,4559.86
  Bottom Layer w6: v1@9075.7,4515.36 9049.8,4489.36 9049.8,3813.26 9089.8,3773.36 9360.2,3773.36 9463.4,3670.16 9463.4,3448.76 9438.7,3424.07 J2.20@9438.72,3366.46
PF9: J2.21 RP2.1 U1.21 | length 2538.1
  Top Layer w6: RP2.1@8962.73,4409.23 ccw(c8963.43,4409.94) RP2.1@8963.43,4408.94 ; RP2.1@8963.4,4408.97 8990.2,4408.97 ; 8990.17,4408.94 ccw(c8990.17,4426.26) 9002.41,4414.02 v1(9071.75,4483.35) 9107.83,4519.44 cw(c9157.85,4469.42) 9157.85,4540.16 ; 9157.8,4540.16 U1.21@9881.43,4540.15
  Bottom Layer w6: v1@9071.7,4483.36 9073.8,4481.27 9073.8,3820.16 9105.6,3788.36 9375.9,3788.36 9485.8,3678.47 9485.8,3319.47 J2.21@9538.72,3266.46
PF10: J2.22 R21.1 U1.22 | length 2444.9
  Top Layer w6: R21.1@8952.23,4353.24 ccw(c8952.23,4417.81) 8997.9,4372.15 9131.61,4506.26 cw(c9165.9,4471.97) 9165.9,4520.47 U1.22@9881.43,4520.47 ; v1(9108.76,4483.02) cw(c9109.72,4483.02) v1@9109.04,4483.69
  Bottom Layer w6: v1(9108.76,4483.02) 9108.76,3837.25 9129.64,3816.37 9395.59,3816.37 9516.94,3695.02 9516.94,3450.74 9538.72,3428.96 J2.22@9538.72,3366.46
PF11: J2.49 U1.49 | length 1497.2
  Top Layer w6: U1.49@10191.47,4171.06 10191.5,3895.57 10271.9,3815.16 10744,3815.16 10897.8,3661.36 10897.8,3413.36 10889.8,3405.36 10889.8,3315.47 J2.49@10938.72,3266.46
PF12: J2.50 U1.50 | length 1445.9
  Top Layer w6: U1.50@10211.16,4171.06 10211.2,3910.07 10291.5,3829.76 10787.5,3829.76 10998.4,3618.86 10998.4,3426.16 J2.50@10938.72,3366.46
PF13: J2.53 U1.53 | length 1575.8
  Top Layer w6: U1.53@10270.21,4171.06 10270.2,3923.86 10348.5,3845.57 10874.1,3845.57 11094.1,3625.57 11094.1,3409.36 11089.8,3405.07 11089.8,3315.47 J2.53@11138.72,3266.46
PF14: J2.54 U1.54 | length 1544.8
  Top Layer w6: U1.54@10289.9,4171.06 10289.9,3940.16 10369.6,3860.47 10960.7,3860.47 11189.8,3631.36 11189.8,3478.26 11138.7,3427.16 J2.54@11138.72,3366.46
PF15: J2.55 U1.55 | length 1683.1
  Top Layer w6: U1.55@10309.58,4171.06 10309.6,3950.47 10385,3875.07 11031.6,3875.07 11205.8,3700.86 11205.8,3442.26 11187.8,3424.26 11187.8,3317.47 J2.55@11238.72,3266.46
PG0: J2.56 U1.56 | length 1620.4
  Top Layer w6: U1.56@10329.27,4171.06 10329.3,3960.26 10399.9,3889.66 11060.2,3889.66 11301.8,3648.07 11301.8,3487.76 11238.7,3424.66 J2.56@11238.72,3366.46
PG1: J2.57 U1.57 | length 1733
  Top Layer w6: U1.57@10348.95,4171.06 10349,3966.86 10411.6,3904.36 11084.5,3904.36 11319.1,3669.76 11319.1,3443.26 11289.8,3413.97 11289.8,3315.47 J2.57@11338.72,3266.46
PG2: J1.15 U1.87 | length 1675.9
  Top Layer w6: U1.87@10718.05,4520.47 10868.8,4520.47 v1(10883.75,4535.35)
  Bottom Layer w6: v1(10883.75,4535.35) 11057.8,4709.36 11057.8,5187.36 11223.8,5353.36 11301,5353.36 11345.8,5398.16 11345.8,5557.36 11387.8,5599.36 11387.8,5715.97 J1.15@11338.7,5765.06
PG3: J1.16 U1.88 | length 1509.4
  Top Layer w6: U1.88@10718.05,4540.15 10858.5,4540.16 v1@10895.7,4577.36
  Bottom Layer w6: v1@10895.7,4577.36 11043.8,4725.36 11043.8,5195.36 11215.8,5367.36 11292.9,5367.36 11329.8,5404.27 11329.8,5591.47 11338.7,5600.36 J1.16@11338.7,5665.06
  other v1: 10895.75,4577.35
PG4: J1.17 U1.89 | length 1605.8
  Top Layer w6: U1.89@10718.1,4559.86 10848.2,4559.86 v1@10861.7,4573.36
  Bottom Layer w6: v1@10861.7,4573.36 11029.8,4741.36 11029.8,5205.36 11207.8,5383.36 11287.2,5383.36 11313.8,5409.97 11313.8,5563.36 11287.8,5589.36 11287.8,5715.97 J1.17@11238.7,5765.06
  other v1: 10861.75,4573.35
PG5: J1.18 U1.90 | length 1469.5
  Top Layer w6: U1.90@10718.05,4579.52 10839.9,4579.47 v1@10869.7,4609.36
  Bottom Layer w6: v1@10869.7,4609.36 11013.8,4753.36 11013.8,5209.36 11201.8,5397.36 11280.7,5397.36 11299.8,5416.36 11299.8,5543.36 11238.7,5604.36 J1.18@11238.7,5665.06
  other v1: 10869.75,4609.35
PG6: J1.19 R22.1 U1.91 | length 4051.1
  Top Layer w6: R22.1@8670.5,4039.36 v1(9608.75,4039.36) ; v1@10558.24,4598.07 10717.01,4598.07 U1.91@10718.05,4599.2 10831.6,4599.16 v1@10881.7,4649.36
  Bottom Layer w6: v1(9608.75,4039.36) 10527.8,4039.36 10558.24,4069.8 v1@10558.24,4598.07 ; v1@10881.7,4649.36 10997.8,4765.36 10997.8,5219.36 11205.8,5427.36 11205.8,5605.36 11187.8,5623.36 11187.8,5715.97 J1.19@11138.7,5765.06
  other v1: 10558.29,4598.06 10881.75,4649.35
PG7: J1.20 U1.92 | length 1326
  Top Layer w6: U1.92@10718.05,4618.9 10823.3,4618.86 v1(10847.75,4643.35)
  Bottom Layer w6: v1(10847.75,4643.35) 10983,4778.56 10983,5226.56 11191.8,5435.36 11191.8,5542.16 11138.7,5595.27 J1.20@11138.7,5665.06
PG8: J1.21 U1.93 | length 1370
  Top Layer w6: U1.93@10718.05,4638.57 10808.73,4638.56 v1(10812.42,4642.19)
  Bottom Layer w6: v1(10812.42,4642.19) 10814.64,4642.2 10968.4,4795.97 10968.4,5263.97 11106.7,5402.27 11106.7,5590.16 11089.8,5607.06 11089.8,5713.97 J1.21@11038.7,5765.06
PG9: J1.52 U1.124 | length 1212.9
  Top Layer w6: J1.52@9555.75,5648 J1.52@9538.72,5665.03 9652.4,5551.36 9783.7,5551.36 9841.8,5493.27 9841.8,5435.36 9917.8,5359.36 10120.7,5359.36 10349,5131.06 U1.124@10348.95,5007.69
PG10: J1.53 U1.125 | length 1371.6
  Top Layer w6: J1.53@9438.7,5765.06 9485.8,5717.97 9485.8,5631.36 9517.8,5599.36 9567.8,5599.36 9643.8,5523.36 9715.7,5523.36 9735.8,5503.36 9735.8,5428.56 9820.9,5343.36 10117.7,5343.36 10329.3,5131.77 U1.125@10329.27,5007.69
PG11: J1.54 RP3.3 U1.126 | length 3408.6
  Top Layer w6: J1.54@9438.7,5665.06 9438.7,5648.36 9507.7,5579.36 9555.8,5579.36 9641.8,5493.36 9641.8,5409.36 9723.8,5327.36 10112.83,5327.36 10308.75,5131.45 v1(10308.75,5087.35) ; v1(10308.75,5087.35) 10308.8,5008.56 U1.126@10309.58,5007.69 ; v1@10456.7,5170.36 10496.69,5210.35 11437.71,5210.35 11442.66,5215.31 11620.39,5215.31 11689.09,5284.02 11912.22,5284.02 12059.57,5431.37 12220.57,5431.37 12244.9,5407.05 RP3.3@12244.89,5361.35
  Bottom Layer w6: v1(10308.75,5087.35) 10391.75,5170.35 v1(10456.75,5170.35)
PG12: J1.55 U1.127 | length 1463.6
  Top Layer w6: J1.55@9338.7,5765.06 9387.8,5715.97 9387.8,5641.36 9423.8,5605.36 9457.8,5605.36 9539.8,5523.36 9539.8,5379.36 9605.8,5313.36 10104.8,5313.36 10289.9,5128.16 U1.127@10289.9,5007.69
PG13: J1.56 RP3.2 U1.128 | length 3954.6
  Top Layer w6: J1.56@9338.7,5665.06 9279,5605.36 9227.8,5605.36 9173.8,5551.37 9173.8,5345.36 9223.81,5295.35 10102.84,5295.35 10268.75,5129.44 v1(10268.75,5080.35) ; v1(10268.75,5080.35) 10268.8,5009.16 U1.128@10270.21,5007.69 ; v1(10438.75,5199.35) 10461.75,5222.35 11428.04,5222.35 11432.99,5227.31 11608.72,5227.31 11678.82,5297.41 11908.55,5297.41 12058.58,5447.35 12246.82,5447.35 12280.3,5413.75 RP3.2@12280.33,5361.35
  Bottom Layer w6: v1(10268.75,5080.35) 10387.75,5199.35 v1(10438.75,5199.35)
PG14: J1.57 RP3.1 U1.129 | length 4041.3
  Top Layer w6: J1.57@9238.7,5765.06 9189.8,5716.06 9189.8,5619.36 9157.8,5587.36 9157.8,5335.06 9213.5,5279.36 10097.6,5279.36 10249.4,5127.56 10249.4,5106.36 10249.4,5008.77 U1.129@10250.53,5007.69 ; v1(10417.75,5221.35) 10439.16,5221.36 10452.15,5234.35 11417.19,5234.35 11425.54,5242.71 11602.45,5242.71 11674.49,5314.75 11908.92,5314.75 12053.52,5459.35 12263.52,5459.35 12311.8,5411.06 12311.8,5365.36 RP3.1@12315.7,5361.36
  Bottom Layer w6: v1@10249.4,5106.36 10364.4,5221.36 v1(10417.75,5221.35)
  other v1: 10249.39,5106.32
PG15: J1.60 R75.1 U1.132 U4.10 | length 4605.9
  Top Layer w6: J1.60@9138.7,5665.06 9138.7,5326.37 9201.8,5263.36 10091.8,5263.36 10192.75,5162.41 v1(10192.75,5090.35) ; U1.132@10191.47,5007.69 10192.8,5008.86 v1(10192.75,5090.35) ; v1(10392.75,5242.35) 10407.5,5242.36 10411.49,5246.35 11408.31,5246.35 11417.6,5255.65 11591.75,5255.65 11668.18,5332.09 11908.92,5332.09 12049.18,5472.35 12290.7,5472.35 12330.11,5432.95 v1@12331.68,5432.95 ; U4.10@12479.07,5042.26 12527.7,5042.27 v1(12554.75,5069.35)
  Bottom Layer w6: v1(10192.75,5090.35) 10195.75,5090.35 10347.75,5242.35 v1(10392.75,5242.35) ; v1(12331.68,5432.95) 12331.73,5133.44 12395.8,5069.36 v1(12554.75,5069.35) R75.1@12595.3,5069.36
PH0/HEXT_IN: R1.2 U1.23 | length 360.8
  Top Layer w6: R1.2@9597.3,4447.36 9597.3,4447.56 v1(9643.42,4447.56) 9696.6,4500.77 U1.23@9881.43,4500.78
  Bottom Layer w6: 9589,4447.36 9643.2,4447.36 v1(9643.42,4447.56)
PH0_E: J2.23 | length 1268.5
  Bottom Layer w6: 9544.6,4447.36 9512.8,4447.36 9508.3,4442.86 9508.3,4366.77 9524,4351.06 9524,3766.76 9589,3701.66 9589,3316.16 J2.23@9638.72,3266.46
PH1/HEXT_OUT: R3.2 U1.24 | length 371.7
  Top Layer w6: R3.2@9597.3,4393.36 9633.7,4393.36 v1(9637.75,4397.35) 9721.5,4481.06 U1.24@9881.43,4481.1
  Bottom Layer w6: 9589,4391.36 9595,4397.36 v1(9637.75,4397.35)
PH1_E: J2.24 | length 1063.9
  Bottom Layer w6: 9544.6,4391.36 9544.6,3774.47 9610.7,3708.36 9610.7,3453.26 9638.7,3425.26 J2.24@9638.72,3366.46
PH2: J1.34 U1.106 | length 986.1
  Top Layer w6: U1.106@10718.05,4894.48 10764.9,4894.47 10779.7,4909.27 v1@10779.7,4948.77
  Bottom Layer w6: J1.34@10438.7,5665.06 10440.1,5665.06 10591.4,5513.77 10591.4,5413.27 10637.9,5366.77 10672.9,5366.77 10701.3,5338.36 10701.3,5049.2 10779.7,4970.8 v1@10779.7,4948.77
  other v1: 10779.71,4948.73
PH3: J2.71 R32.1 U1.71 | length 3000.9
  Top Layer w6: U1.71@10624.6,4171.06 10624.6,4101.06 10656.07,4069.71 11018.15,4069.71 11030.68,4082.25 11095.96,4082.25 11107.32,4070.89 11329.77,4070.89 11527.1,3873.57 11527.1,3667.76 11627.9,3566.97 11902.2,3566.97 11989.8,3479.26 11989.8,3315.47 J2.71@12038.72,3266.46 ; v1(12188.66,3834.09) 12188.9,3834.36 R32.1@12503,3834.36
  Bottom Layer w6: J2.71@12038.72,3266.46 12106.31,3334.05 12106.31,3749.78 12188.66,3832.13 v1(12188.66,3834.09)
QSPI1_IO0: RP2.7 U8.5 | length 130
  Top Layer w6: U8.5@8765.7,4423.02 cw(c8817.99,4370.75) 8817.99,4444.66 RP2.7@8889.9,4444.66
QSPI1_IO1: RP2.8 U8.2 | length 437
  Top Layer w5.98: U8.2@8665.7,4155.31 v3(8665.72,4221.8)
  Top Layer w6: v3(8730.13,4360.88) 8771.73,4360.88 ccw(c8771.73,4417.38) 8811.68,4377.42 8831.9,4397.64 cw(c8860.15,4369.39) 8860.15,4409.34 ; 8860.1,4409.36 RP2.8@8889.7,4409.36 ; RP2.8@8889.65,4409.34 cw(c8889.65,4408.99) RP2.8@8889.9,4409.23
  Bottom Layer w6: v3(8665.72,4221.8) 8709.64,4221.79 ccw(c8709.64,4242.29) 8730.13,4242.29 v3(8730.13,4360.88)
  other v3: 8665.72,4221.8
QSPI1_IO2: RP2.6 U8.3 | length 547.9
  Top Layer w5.98: v3@8702.2,4252.56 8715.7,4238.97 U8.3@8715.7,4155.31
  Top Layer w6: v3(8691.51,4491.69) 8796.46,4491.69 cw(c8796.46,4470.16) 8811.68,4485.38 ccw(c8824.42,4498.11) 8824.42,4480.1 ; 8824.4,4480.06 RP2.6@8889.9,4480.1
  Bottom Layer w5.98: v3(8691.51,4491.69) 8691.51,4263.16 v3(8702.15,4252.52)
QSPI1_IO3: RP2.5 U8.7 | length 308.9
  Top Layer w6: U8.7@8665.12,4423.62 ccw(c8665.72,4423.62) U8.7@8665.7,4423.02 ; U8.7@8665.1,4423.66 8665.1,4495.27 cw(c8685.42,4495.23) 8685.42,4515.53 RP2.5@8889.9,4515.56
QSPI1_NSS: R22.2 U8.1 | length 116
  Top Layer w6: R22.2@8615.5,4039.36 8615.7,4039.57 U8.1@8615.7,4155.31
